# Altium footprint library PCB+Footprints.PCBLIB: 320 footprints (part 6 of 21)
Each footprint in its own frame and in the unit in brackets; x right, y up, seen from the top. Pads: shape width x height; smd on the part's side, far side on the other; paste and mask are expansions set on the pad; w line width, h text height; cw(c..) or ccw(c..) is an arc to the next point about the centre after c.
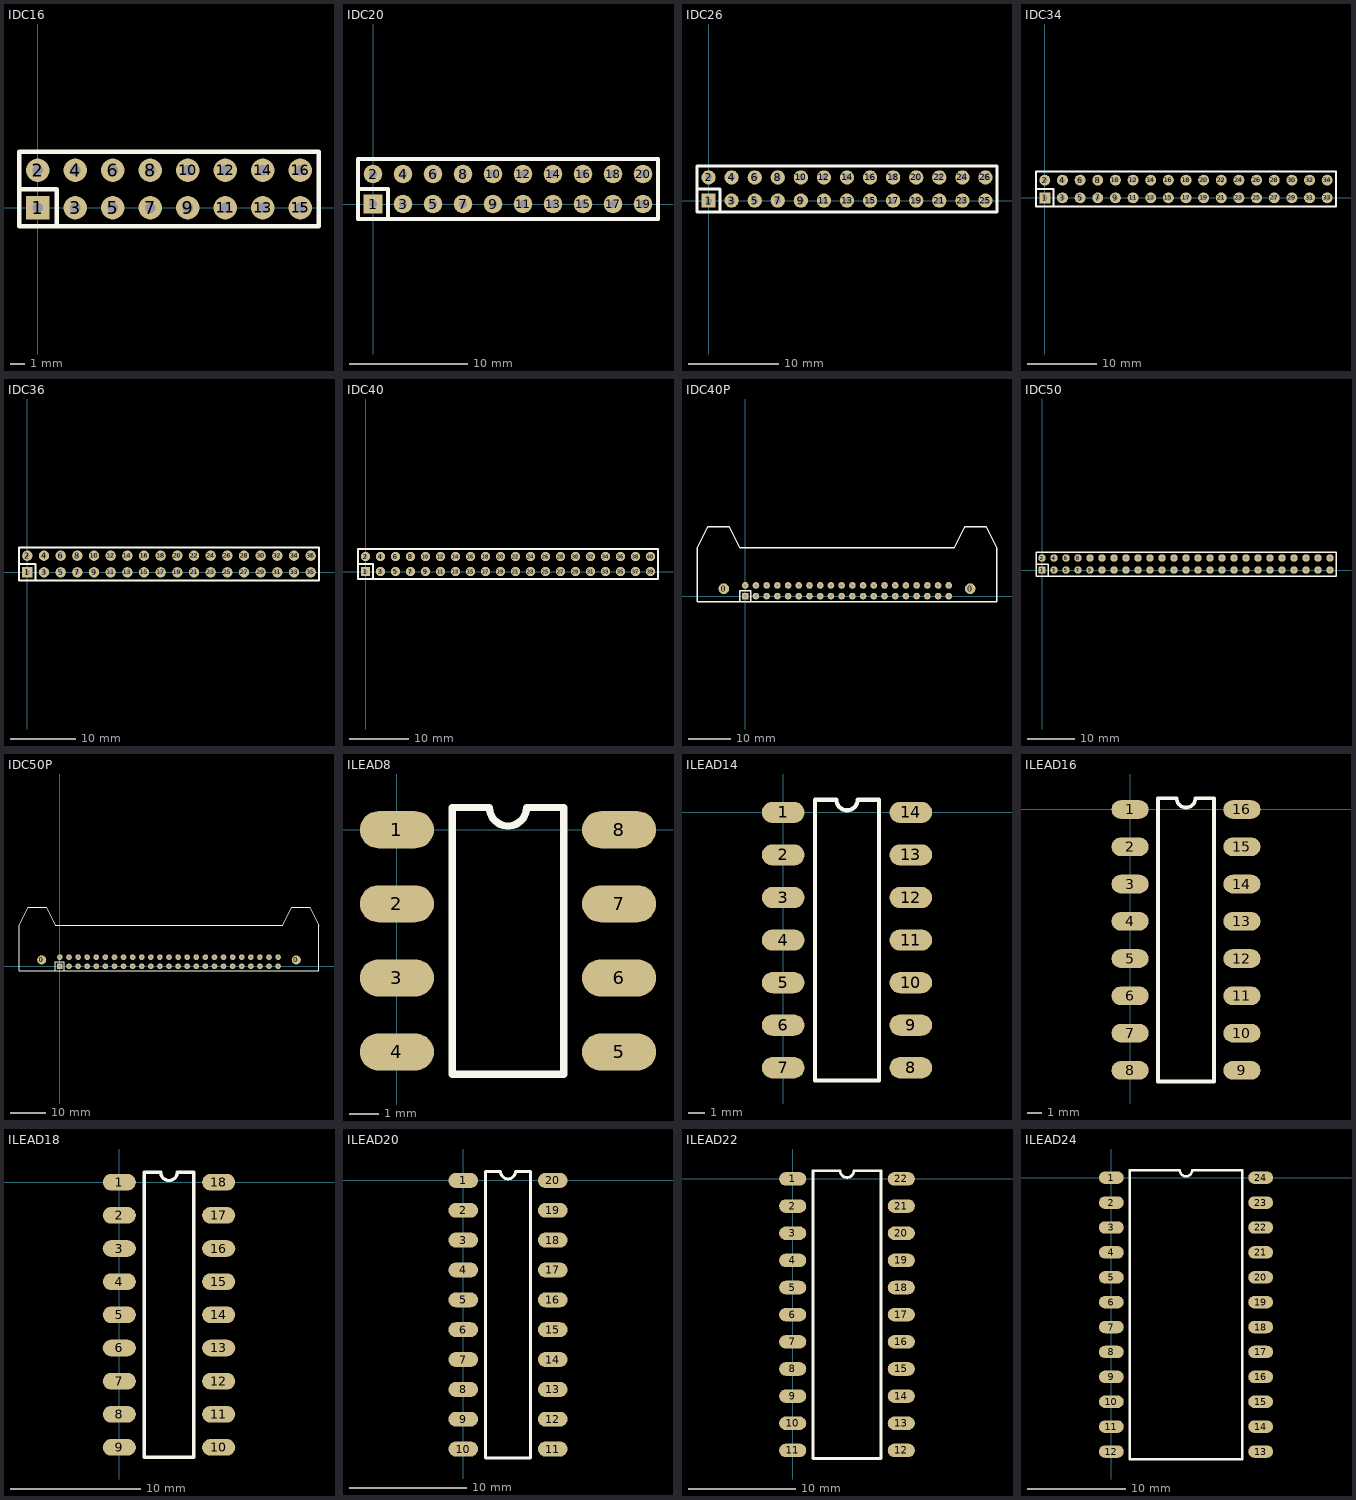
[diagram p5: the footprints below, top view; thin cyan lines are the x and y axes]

## IDC16 [mil]
pads (16):
  rect 62x62 hole 28: 1(0,0)
  round 62 hole 28: 2(0,100) 3(100,0) 4(100,100) 5(200,0) 6(200,100) 7(300,0) 8(300,100) 9(400,0) 10(400,100) 11(500,0) 12(500,100) 13(600,0) 14(600,100) 15(700,0) 16(700,100)
TopOverlay:
  lines w12: -50,50 50,50 50,-50 ; -50,-50 750,-50 750,150 -50,150 -50,-50

## IDC20 [mil]
pads (20):
  rect 62x62 hole 28: 1(0,0)
  round 62 hole 28: 2(0,100) 3(100,0) 4(100,100) 5(200,0) 6(200,100) 7(300,0) 8(300,100) 9(400,0) 10(400,100) 11(500,0) 12(500,100) 13(600,0) 14(600,100) 15(700,0) 16(700,100) 17(800,0) 18(800,100) 19(900,0) 20(900,100)
TopOverlay:
  lines w12: -50,50 50,50 50,-50 ; -50,-50 950,-50 950,150 -50,150 -50,-50

## IDC26 [mil]
pads (26):
  rect 62x62 hole 28: 1(0,0)
  round 62 hole 28: 2(0,100) 3(100,0) 4(100,100) 5(200,0) 6(200,100) 7(300,0) 8(300,100) 9(400,0) 10(400,100) 11(500,0) 12(500,100) 13(600,0) 14(600,100) 15(700,0) 16(700,100) 17(800,0) 18(800,100) 19(900,0) 20(900,100) 21(1000,0) 22(1000,100) 23(1100,0) 24(1100,100) 25(1200,0) 26(1200,100)
TopOverlay:
  lines w12: -50,50 50,50 50,-50 ; -50,-50 1250,-50 1250,150 -50,150 -50,-50

## IDC34 [mil]
pads (34):
  rect 62x62 hole 28: 1(0,0)
  round 62 hole 28: 2(0,100) 3(100,0) 4(100,100) 5(200,0) 6(200,100) 7(300,0) 8(300,100) 9(400,0) 10(400,100) 11(500,0) 12(500,100) 13(600,0) 14(600,100) 15(700,0) 16(700,100) 17(800,0) 18(800,100) 19(900,0) 20(900,100) 21(1000,0) 22(1000,100) 23(1100,0) 24(1100,100) 25(1200,0) 26(1200,100) 27(1300,0) 28(1300,100) 29(1400,0) 30(1400,100) 31(1500,0) 32(1500,100) 33(1600,0) 34(1600,100)
TopOverlay:
  lines w12: -50,50 50,50 50,-50 ; -50,-50 1650,-50 1650,150 -50,150 -50,-50

## IDC36 [mil]
pads (36):
  rect 62x62 hole 28: 1(0,0)
  round 62 hole 28: 2(0,100) 3(100,0) 4(100,100) 5(200,0) 6(200,100) 7(300,0) 8(300,100) 9(400,0) 10(400,100) 11(500,0) 12(500,100) 13(600,0) 14(600,100) 15(700,0) 16(700,100) 17(800,0) 18(800,100) 19(900,0) 20(900,100) 21(1000,0) 22(1000,100) 23(1100,0) 24(1100,100) 25(1200,0) 26(1200,100) 27(1300,0) 28(1300,100) 29(1400,0) 30(1400,100) 31(1500,0) 32(1500,100) 33(1600,0) 34(1600,100) 35(1700,0) 36(1700,100)
TopOverlay:
  lines w12: -50,50 50,50 50,-50 ; -50,-50 -50,150 1750,150 1750,-50 -50,-50

## IDC40 [mil]
pads (40):
  rect 62x62 hole 28: 1(0,0)
  round 62 hole 28: 2(0,100) 3(100,0) 4(100,100) 5(200,0) 6(200,100) 7(300,0) 8(300,100) 9(400,0) 10(400,100) 11(500,0) 12(500,100) 13(600,0) 14(600,100) 15(700,0) 16(700,100) 17(800,0) 18(800,100) 19(900,0) 20(900,100) 21(1000,0) 22(1000,100) 23(1100,0) 24(1100,100) 25(1200,0) 26(1200,100) 27(1300,0) 28(1300,100) 29(1400,0) 30(1400,100) 31(1500,0) 32(1500,100) 33(1600,0) 34(1600,100) 35(1700,0) 36(1700,100) 37(1800,0) 38(1800,100) 39(1900,0) 40(1900,100)
TopOverlay:
  lines w12: -50,50 50,50 50,-50 ; -50,-50 -50,150 1950,150 1950,-50 -50,-50

## IDC40P [mil]
pads (42):
  round 100 hole 28: 0(-200,70) 0(2100,70)
  rect 62x62 hole 28: 1(0,0)
  round 62 hole 28: 2(0,100) 3(100,0) 4(100,100) 5(200,0) 6(200,100) 7(300,0) 8(300,100) 9(400,0) 10(400,100) 11(500,0) 12(500,100) 13(600,0) 14(600,100) 15(700,0) 16(700,100) 17(800,0) 18(800,100) 19(900,0) 20(900,100) 21(1000,0) 22(1000,100) 23(1100,0) 24(1100,100) 25(1200,0) 26(1200,100) 27(1300,0) 28(1300,100) 29(1400,0) 30(1400,100) 31(1500,0) 32(1500,100) 33(1600,0) 34(1600,100) 35(1700,0) 36(1700,100) 37(1800,0) 38(1800,100) 39(1900,0) 40(1900,100)
TopOverlay:
  lines w12: -50,-50 -50,50 50,50 50,-50 ; -450,-50 -450,450 -350,650 -150,650 -50,450 1950,450 2050,650 2250,650 2350,450 2350,-50 -450,-50

## IDC50 [mil]
pads (50):
  rect 62x62 hole 28: 1(0,0)
  round 62 hole 28: 2(0,100) 3(100,0) 4(100,100) 5(200,0) 6(200,100) 7(300,0) 8(300,100) 9(400,0) 10(400,100) 11(500,0) 12(500,100) 13(600,0) 14(600,100) 15(700,0) 16(700,100) 17(800,0) 18(800,100) 19(900,0) 20(900,100) 21(1000,0) 22(1000,100) 23(1100,0) 24(1100,100) 25(1200,0) 26(1200,100) 27(1300,0) 28(1300,100) 29(1400,0) 30(1400,100) 31(1500,0) 32(1500,100) 33(1600,0) 34(1600,100) 35(1700,0) 36(1700,100) 37(1800,0) 38(1800,100) 39(1900,0) 40(1900,100) 41(2000,0) 42(2000,100) 43(2100,0) 44(2100,100) 45(2200,0) 46(2200,100) 47(2300,0) 48(2300,100) 49(2400,0) 50(2400,100)
TopOverlay:
  lines w12: -50,50 50,50 50,-50 ; -50,-50 -50,150 2450,150 2450,-50 -50,-50

## IDC50P [mil]
pads (52):
  round 100 hole 28: 0(-200,70) 0(2600,70)
  rect 62x62 hole 28: 1(0,0)
  round 62 hole 28: 2(0,100) 3(100,0) 4(100,100) 5(200,0) 6(200,100) 7(300,0) 8(300,100) 9(400,0) 10(400,100) 11(500,0) 12(500,100) 13(600,0) 14(600,100) 15(700,0) 16(700,100) 17(800,0) 18(800,100) 19(900,0) 20(900,100) 21(1000,0) 22(1000,100) 23(1100,0) 24(1100,100) 25(1200,0) 26(1200,100) 27(1300,0) 28(1300,100) 29(1400,0) 30(1400,100) 31(1500,0) 32(1500,100) 33(1600,0) 34(1600,100) 35(1700,0) 36(1700,100) 37(1800,0) 38(1800,100) 39(1900,0) 40(1900,100) 41(2000,0) 42(2000,100) 43(2100,0) 44(2100,100) 45(2200,0) 46(2200,100) 47(2300,0) 48(2300,100) 49(2400,0) 50(2400,100)
TopOverlay:
  lines w12: -50,-50 -50,50 50,50 50,-50 ; -450,-50 2850,-50 2850,450 2750,650 2550,650 2450,450 -50,450 -150,650 -350,650 -450,450 -450,-50

## ILEAD8 [mil]
pads (8):
  oval 100x50 smd: 1(0,0) 2(0,-100) 3(0,-200) 4(0,-300) 5(300,-300) 6(300,-200) 7(300,-100) 8(300,0)
TopOverlay:
  lines w10: 75,-330 225,-330 225,30 175,30 cw(c150,30) 125,30 75,30 75,-330

## ILEAD14 [mil]
pads (14):
  oval 100x50 smd: 1(0,0) 2(0,-100) 3(0,-200) 4(0,-300) 5(0,-400) 6(0,-500) 7(0,-600) 8(300,-600) 9(300,-500) 10(300,-400) 11(300,-300) 12(300,-200) 13(300,-100) 14(300,0)
TopOverlay:
  lines w10: 75,-630 75,30 125,30 ccw(c150,30) 175,30 225,30 225,-630 75,-630

## ILEAD16 [mil]
pads (16):
  oval 100x50 smd: 1(0,0) 2(0,-100) 3(0,-200) 4(0,-300) 5(0,-400) 6(0,-500) 7(0,-600) 8(0,-700) 9(300,-700) 10(300,-600) 11(300,-500) 12(300,-400) 13(300,-300) 14(300,-200) 15(300,-100) 16(300,0)
TopOverlay:
  lines w10: 75,-730 75,30 125,30 ccw(c150,30) 175,30 225,30 225,-730 75,-730

## ILEAD18 [mil]
pads (18):
  oval 100x50 smd: 1(0,0) 2(0,-100) 3(0,-200) 4(0,-300) 5(0,-400) 6(0,-500) 7(0,-600) 8(0,-700) 9(0,-800) 10(300,-800) 11(300,-700) 12(300,-600) 13(300,-500) 14(300,-400) 15(300,-300) 16(300,-200) 17(300,-100) 18(300,0)
TopOverlay:
  lines w10: 75,-830 75,30 125,30 ccw(c150,30) 175,30 225,30 225,-830 75,-830

## ILEAD20 [mil]
pads (20):
  oval 100x50 smd: 1(0,0) 2(0,-100) 3(0,-200) 4(0,-300) 5(0,-400) 6(0,-500) 7(0,-600) 8(0,-700) 9(0,-800) 10(0,-900) 11(300,-900) 12(300,-800) 13(300,-700) 14(300,-600) 15(300,-500) 16(300,-400) 17(300,-300) 18(300,-200) 19(300,-100) 20(300,0)
TopOverlay:
  lines w10: 75,-930 225,-930 225,30 175,30 cw(c150,30) 125,30 75,30 75,-930

## ILEAD22 [mil]
pads (22):
  oval 100x50 smd: 1(0,0) 2(0,-100) 3(0,-200) 4(0,-300) 5(0,-400) 6(0,-500) 7(0,-600) 8(0,-700) 9(0,-800) 10(0,-900) 11(0,-1000) 12(400,-1000) 13(400,-900) 14(400,-800) 15(400,-700) 16(400,-600) 17(400,-500) 18(400,-400) 19(400,-300) 20(400,-200) 21(400,-100) 22(400,0)
TopOverlay:
  lines w10: 75,-1030 75,30 175,30 ccw(c200,30) 225,30 325,30 325,-1030 75,-1030

## ILEAD24 [mil]
pads (24):
  oval 100x50 smd: 1(0,0) 2(0,-100) 3(0,-200) 4(0,-300) 5(0,-400) 6(0,-500) 7(0,-600) 8(0,-700) 9(0,-800) 10(0,-900) 11(0,-1000) 12(0,-1100) 13(600,-1100) 14(600,-1000) 15(600,-900) 16(600,-800) 17(600,-700) 18(600,-600) 19(600,-500) 20(600,-400) 21(600,-300) 22(600,-200) 23(600,-100) 24(600,0)
TopOverlay:
  lines w10: 75,-1130 75,30 275,30 ccw(c300,30) 325,30 525,30 525,-1130 75,-1130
